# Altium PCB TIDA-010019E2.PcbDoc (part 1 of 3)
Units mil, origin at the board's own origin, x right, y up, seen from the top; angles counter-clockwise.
Board outline 3159.64 x 4813.18 mil, 2 copper layers (Top Layer, Bottom Layer), stack 62 mil thick; 303 components, 177 nets, 861 pads, 1443 vias.
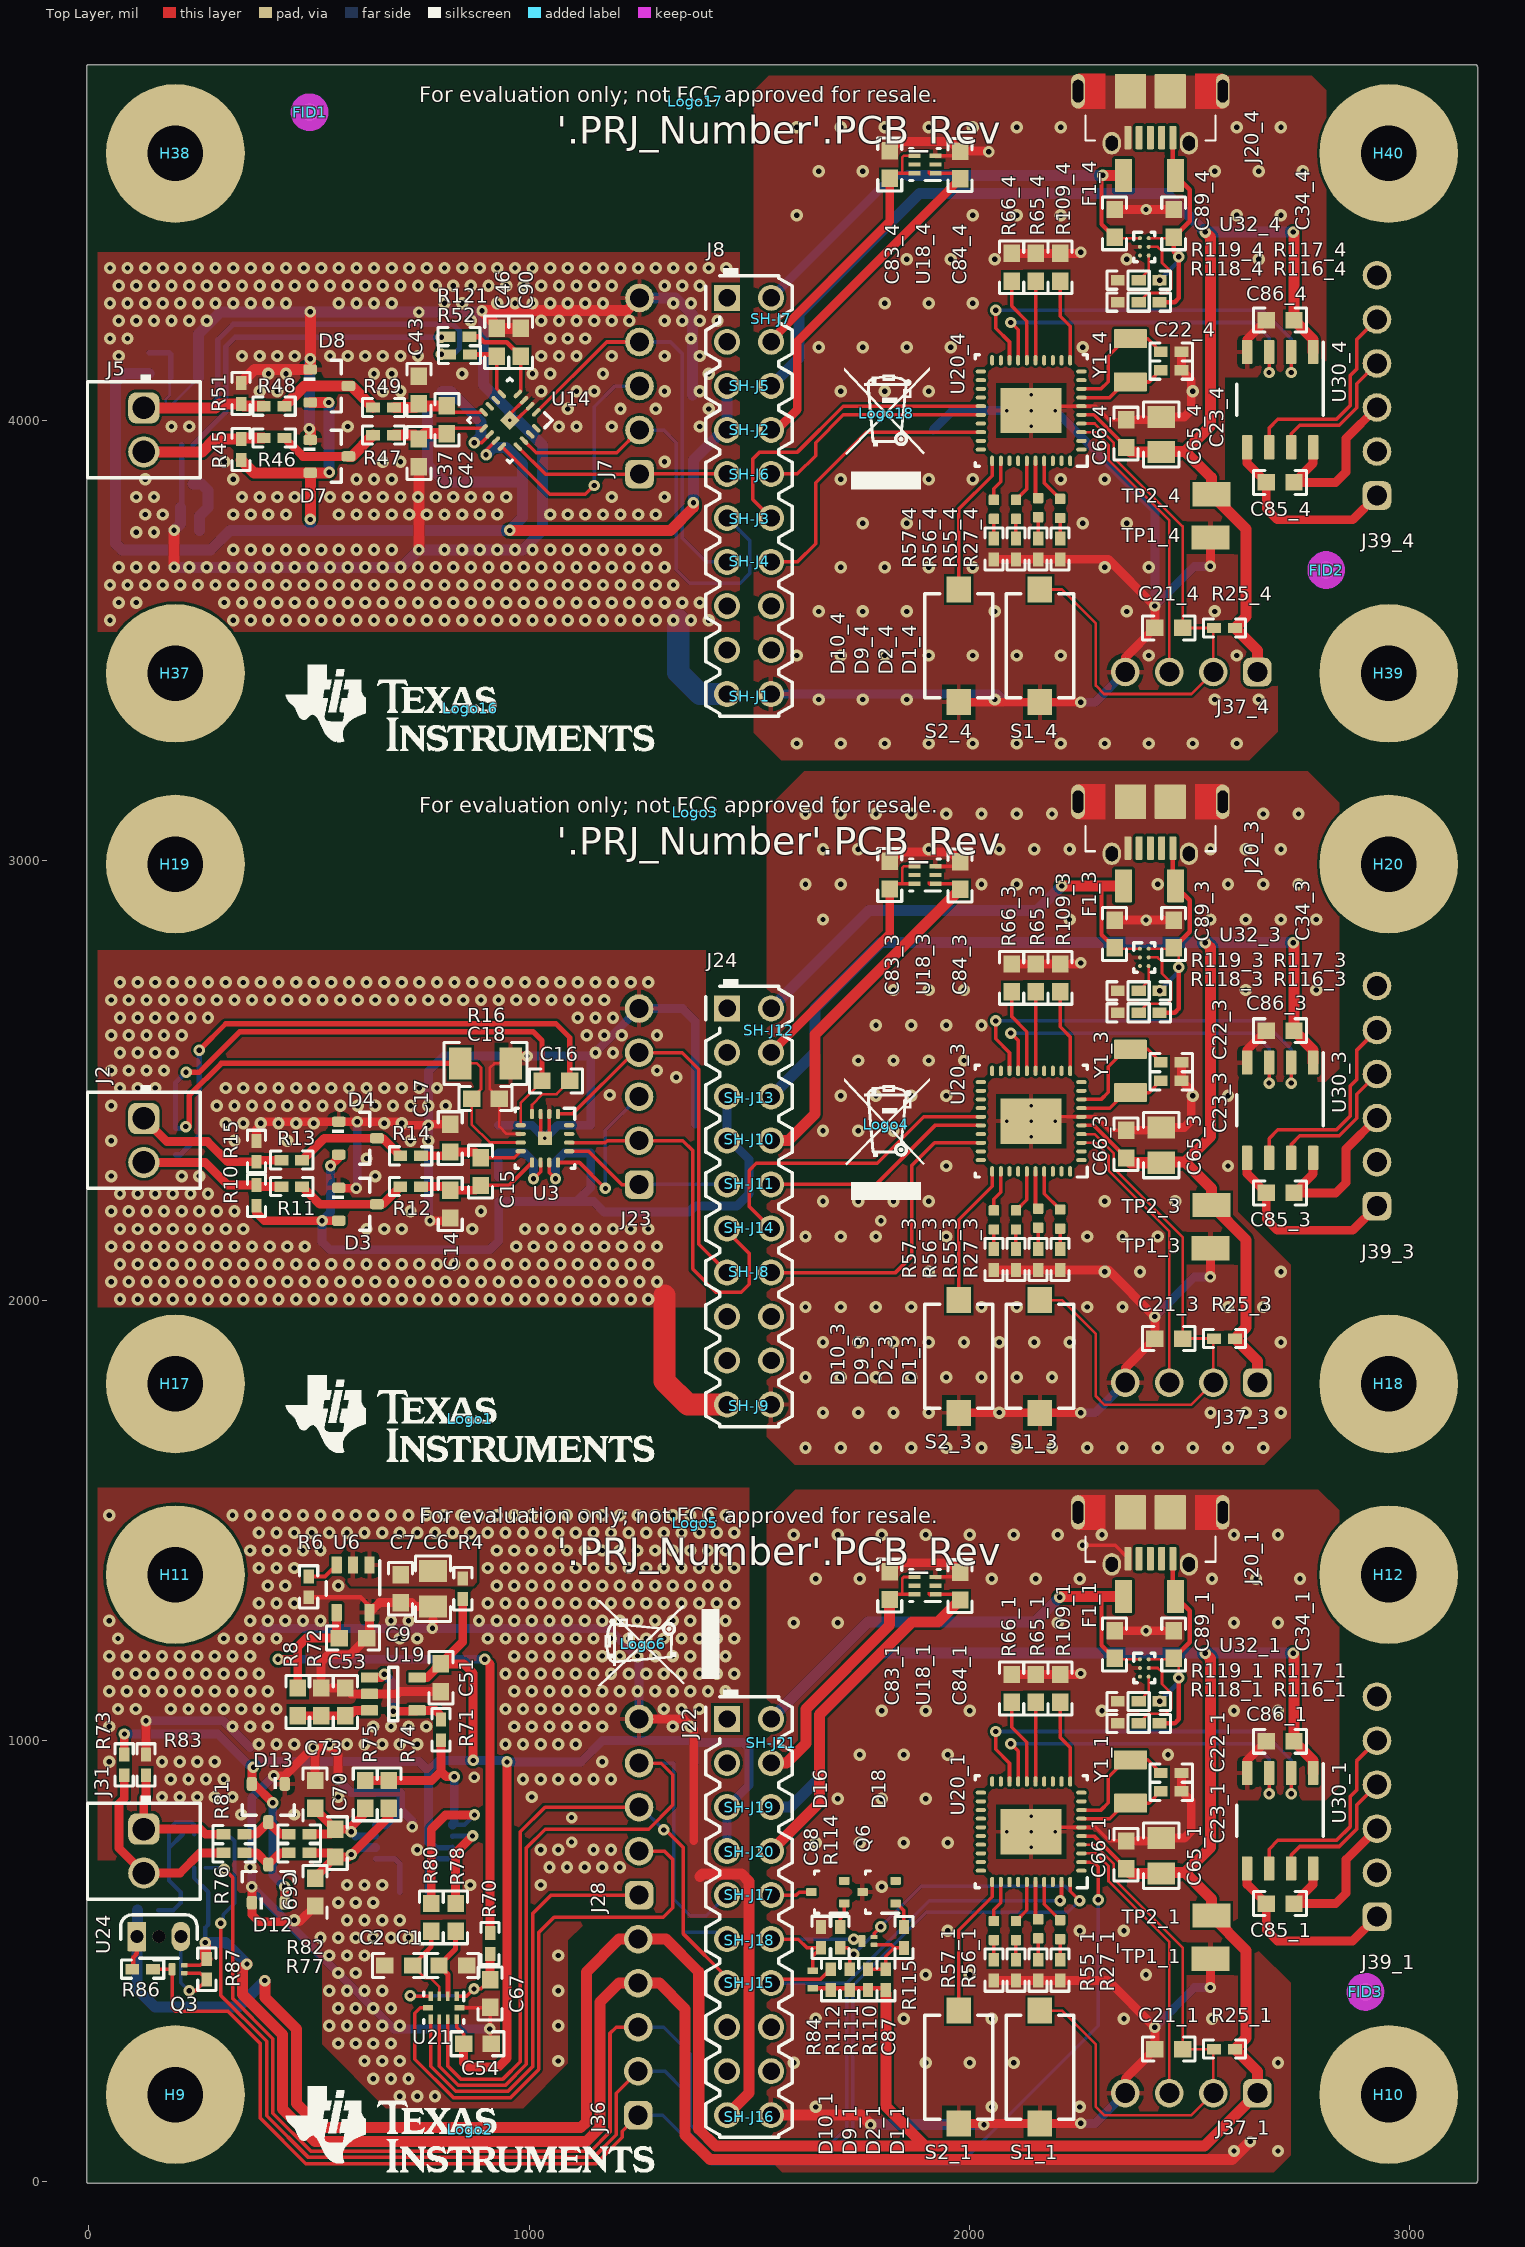
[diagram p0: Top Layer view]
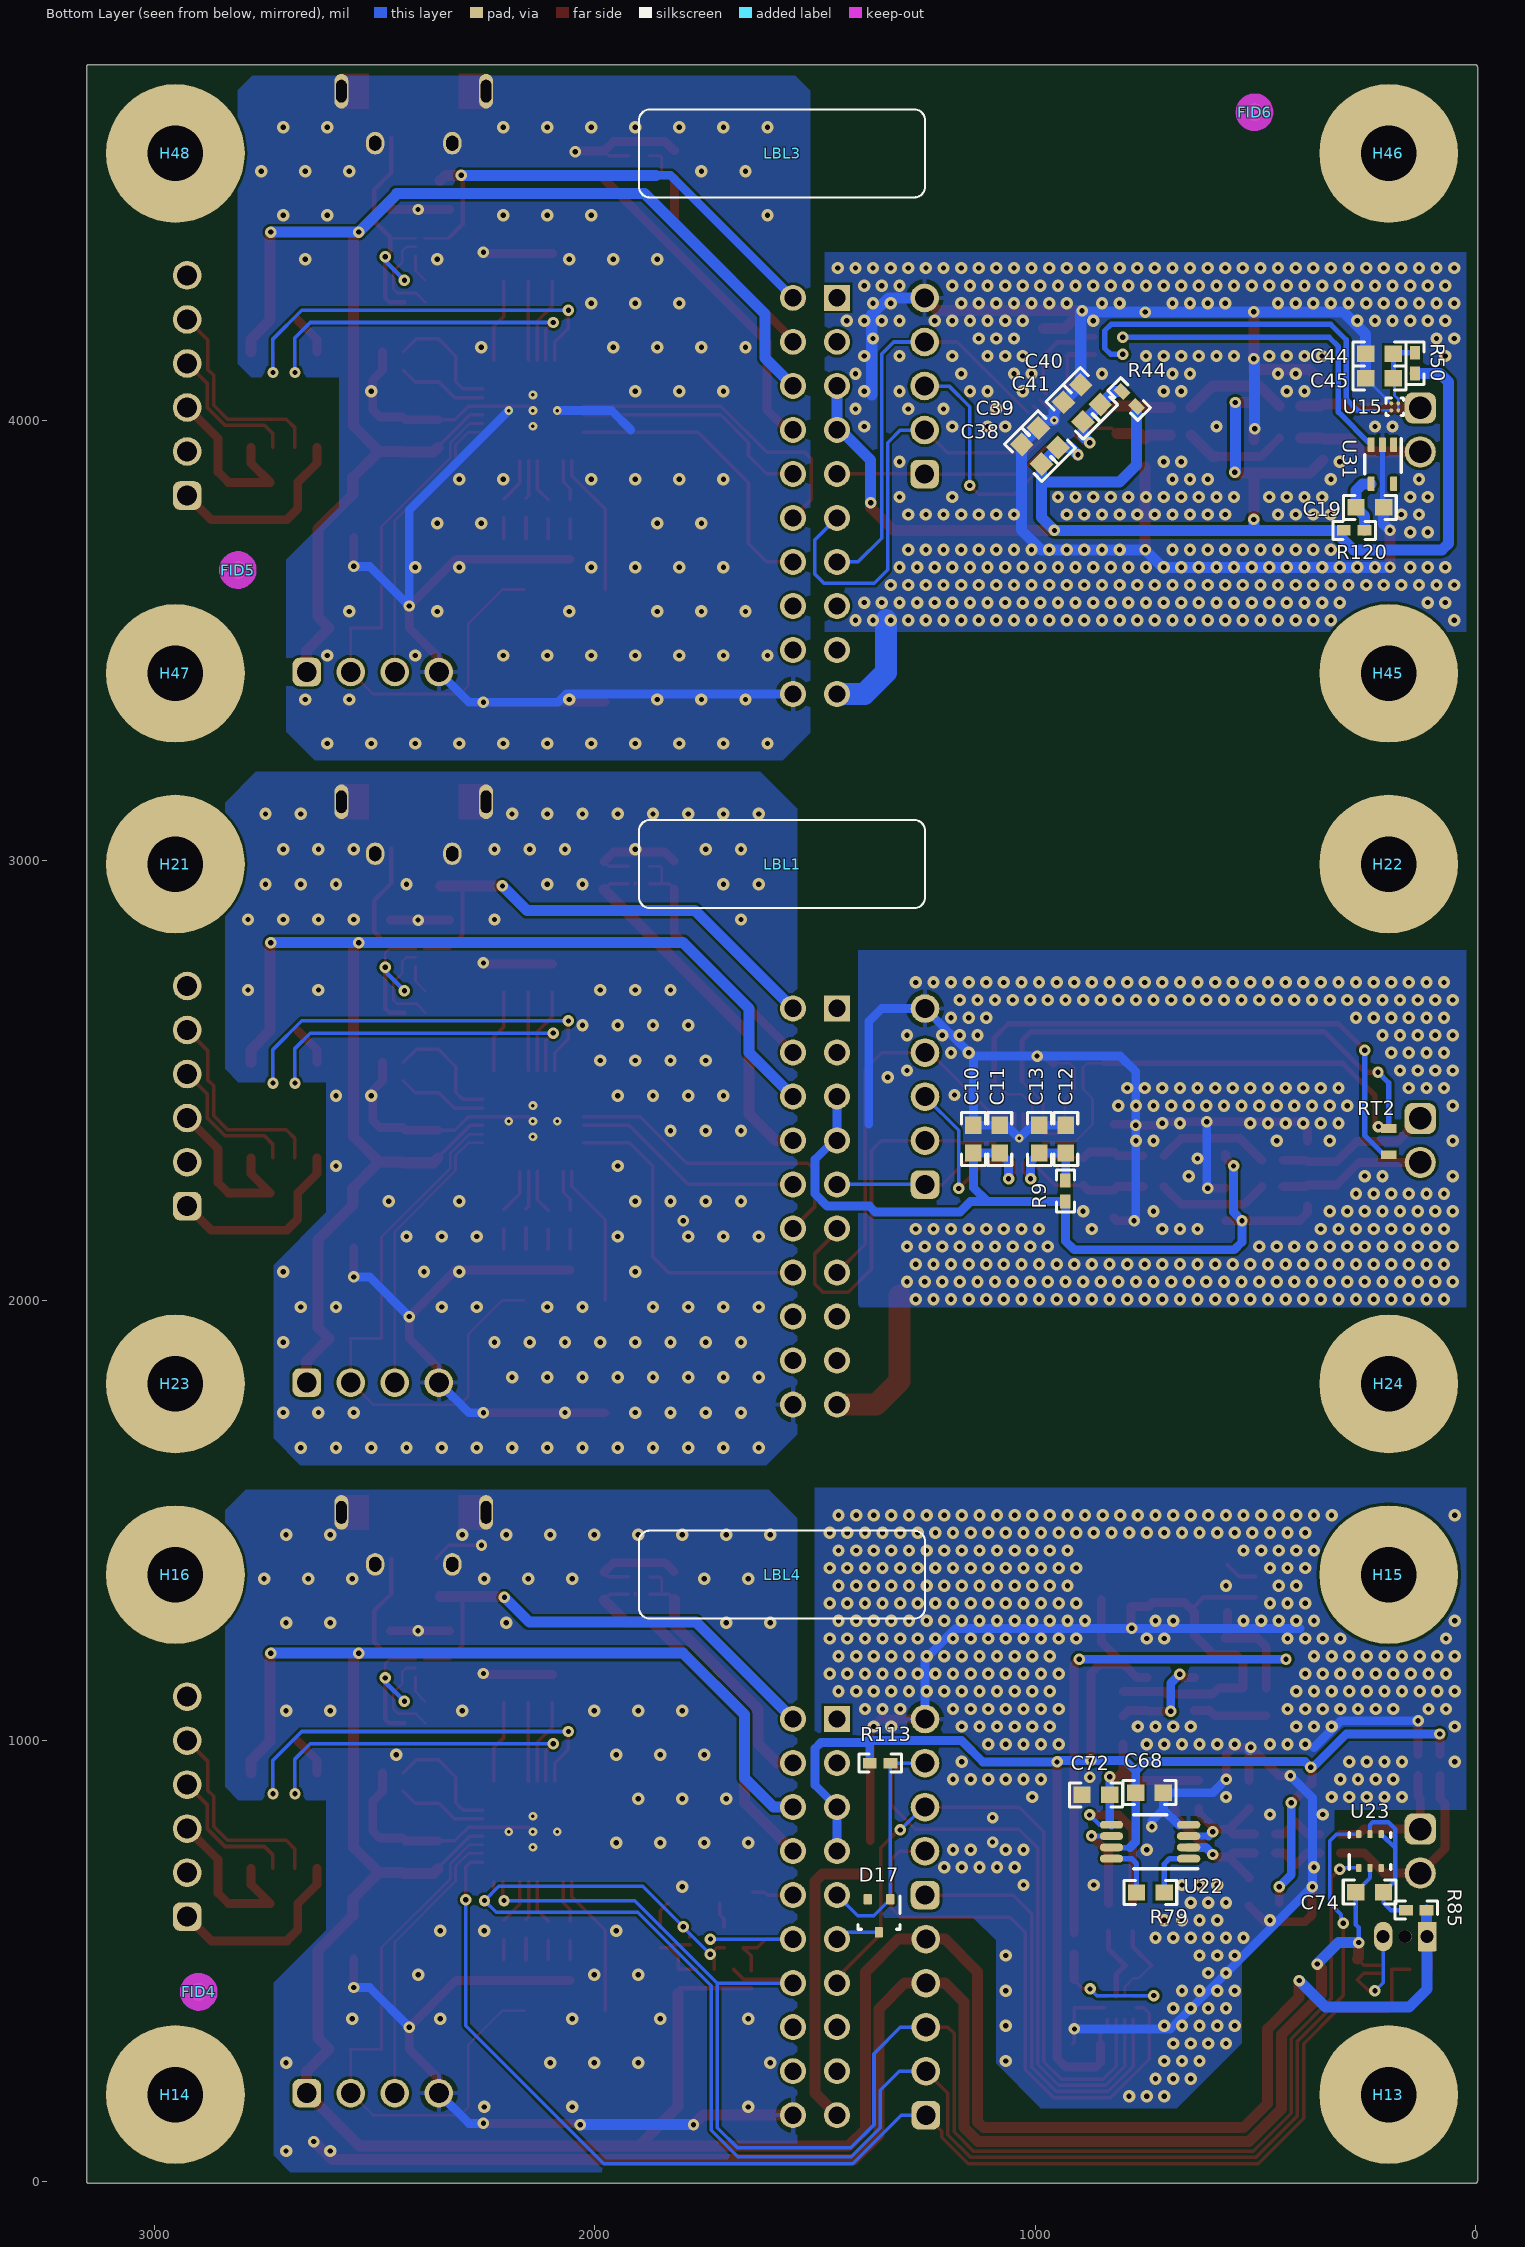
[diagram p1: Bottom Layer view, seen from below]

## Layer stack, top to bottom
Top Solder: solder mask 0.4, Solder Resist, Dk 3.5
Top Layer: signal copper 1.4
Dielectric1: core 59.2, FR-4, Dk 4.8
Bottom Layer: signal copper 1.4
Bottom Solder: solder mask 0.4, Solder Resist, Dk 3.5

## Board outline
-5.01,0 -5.01,4803.15 cw(c0,4803.15) 0,4808.16 3149.61,4808.16 cw(c3149.61,4803.15) 3154.62,4803.15 3154.62,0 cw(c3149.61,0) 3149.61,-5.02 0,-5.02 cw(c0,0)

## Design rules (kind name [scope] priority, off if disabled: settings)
AcuteAngle [All] p1: minimum=4.00000000000000E+0001 checktracksonly=FALSE
AssemblyTestPointUsage [All] p1: valid=2
BoardOutlineClearance BoardOutlineClearance_MountingHoles [OnCopper and InComponentClass('Mounting Holes')] p1: gap=40 ignorepadtopadclearanceinfootprint=FALSE
BoardOutlineClearance BoardOutlineClearance_Poly [OnCopper and IsPoly] p2: gap=25 ignorepadtopadclearanceinfootprint=FALSE
BoardOutlineClearance [OnCopper and Not InComponentClass('Logo') and not InComponentClass('FiducialMark') and not InRegion(1000,500,4000,800) and not InPoly] p3: gap=20 ignorepadtopadclearanceinfootprint=FALSE
Clearance Clearance_Keepouts [((IsTrack Or IsArc) And Not InPoly) And IsFree and IsKeepOut vs ((IsTrack Or IsArc) And Not InPoly) And IsFree and IsKeepOut] p1: gap=0 ignorepadtopadclearanceinfootprint=FALSE
Clearance Clearance_Poly [InPolygon] p2: gap=6 ignorepadtopadclearanceinfootprint=FALSE
Clearance Clearance_FiducialMark [IsKeepOut and InComponentClass('FiducialMark') vs IsPad and InComponentClass('FiducialMark')] p3: gap=0 ignorepadtopadclearanceinfootprint=FALSE
Clearance [All] p4: gap=6 ignorepadtopadclearanceinfootprint=FALSE
ComponentClearance ComponentClearance_1 [InComponent('SH-J*')  or InComponent('J*')] p1: gap=0 collisioncheckmode=3 verticalgap=0 showdistances=FALSE
ComponentClearance ComponentClearance_J21-J25 [InComponent('J21') or InComponent('J25')] p2: gap=0 collisioncheckmode=3 verticalgap=0 showdistances=FALSE
ComponentClearance ComponentClearance_J1-J35 [InComponent('J1') or InComponent('J35')] p3: gap=0 collisioncheckmode=3 verticalgap=0 showdistances=FALSE
ComponentClearance ComponentClearance_J39-J14-U29 [InComponent('J21') or InComponent('J25') or InComponent('U29')] p4: gap=0 collisioncheckmode=3 verticalgap=0 showdistances=FALSE
ComponentClearance ComponentClearance_R117_R119 [InComponent('R117*') or InComponent('R119*')] p5: gap=0 collisioncheckmode=3 verticalgap=0 showdistances=FALSE
ComponentClearance ComponentClearance_R116_R118 [InComponent('R116*') or InComponent('R118*')] p6: gap=0 collisioncheckmode=3 verticalgap=0 showdistances=FALSE
ComponentClearance ComponentClearance_J11-J18 [InComponent('J11') or InComponent('J18')] p7: gap=0 collisioncheckmode=3 verticalgap=0 showdistances=FALSE
ComponentClearance ComponentClearance_J28-J36 [InComponent('J28') or InComponent('J36')] p8: gap=0 collisioncheckmode=3 verticalgap=0 showdistances=FALSE
ComponentClearance ComponentClearance_MountingHoles_FiducialMarks [InComponentClass('Mounting Holes') vs InComponentClass('FiducialMark')] p9: gap=50 collisioncheckmode=3 verticalgap=10 showdistances=FALSE
ComponentClearance ComponentClearance_Shunt [InComponentClass('Header') vs InComponentClass('Shunt')] p10: gap=0 collisioncheckmode=3 verticalgap=0 showdistances=FALSE
ComponentClearance ComponentClearance_Logo [InComponentClass('Logo')] p11: gap=50 collisioncheckmode=3 verticalgap=10 showdistances=FALSE
ComponentClearance ComponentClearance_ScrewToNut [(HasFootprint('NY PMS 440 0025 PH')) vs (HasFootprint('Keystone_1902C'))] p12: gap=4 collisioncheckmode=3 verticalgap=10 showdistances=FALSE
ComponentClearance ComponentClearance_MountingHoles [InComponentClass('Mounting Holes')] p13: gap=50 collisioncheckmode=3 verticalgap=100000 showdistances=FALSE
ComponentClearance ComponentClearance_SmallPassives [HasFootprint('0201*') or HasFootprint('0402*') or HasFootprint('0508') or HasFootprint('0603*') or HasFootprint('0612') or HasFootprint('0805*') or HasFootprint('0815*') or HasFootprint('0830*') or HasFootprint('1206*') or HasFootprint('1210*') or HasFootprint('1808*') or HasFootprint('1812*') or HasFootprint('1825*') or HasFootprint('2010*') or HasFootprint('2220*') or HasFootprint('2225*') or HasFootprint('2512*') or HasFootprint('2728*') or HasFootprint('3518*') vs HasFootprint('0201*') or HasFootprint('0402*') or HasFootprint('0508') or HasFootprint('0603*') or HasFootprint('0612') or HasFootprint('0805*') or HasFootprint('0815*') or HasFootprint('0830*') or HasFootprint('1206*') or HasFootprint('1210*') or HasFootprint('1808*') or HasFootprint('1812*') or HasFootprint('1825*') or HasFootprint('2010*') or HasFootprint('2220*') or HasFootprint('2225*') or HasFootprint('2512*') or HasFootprint('2728*') or HasFootprint('3518*')] p14: gap=14.96 collisioncheckmode=3 verticalgap=10 showdistances=FALSE
ComponentClearance ComponentClearance_THtoSMT [IsThruComponent vs IsSMTComponent] p15: gap=30 collisioncheckmode=3 verticalgap=30 showdistances=FALSE
ComponentClearance ComponentClearance_THtoTH [IsThruComponent vs IsThruComponent] p16: gap=30 collisioncheckmode=3 verticalgap=30 showdistances=FALSE
ComponentClearance [All] p17: gap=25 collisioncheckmode=3 verticalgap=10 showdistances=FALSE
DiffPairsRouting [All] p1: maxlimit=100 minlimit=10 mostfreqgap=10 toplayer_minwidth=15 toplayer_maxwidth=15 toplayer_prefwidth=15 bottomlayer_minwidth=15 bottomlayer_maxwidth=15 bottomlayer_prefwidth=15 maxuncoupledlength=1000
FabricationTestPointUsage TestPointUsage [All] p1: valid=2 allowmultiple=FALSE
FabricationTestpoint Testpoint [All] p1: side=3 testpointundercomponent=TRUE minsize=40 maxsize=100 preferedsize=60 minholesize=0 maxholesize=40 preferedholesize=32 testpointgrid=1 allowsidetop=TRUE allowsidebottom=TRUE usegrid=TRUE gridtolerance=0.01
FanoutControl Fanout_LCC [IsLCC] p1: bgadir=Out bgaviamode=Centered fanoutstyle=Auto fanoutdirection=Alternating viagrid=1 // Fanout_LCC (Default Rule)
FanoutControl Fanout_BGA [IsBGA] p2: bgadir=Out bgaviamode=Centered fanoutstyle=Auto fanoutdirection=Alternating viagrid=1 // Fanout_BGA (Default Rule)
FanoutControl Fanout_Default [All] p4: bgadir=Out bgaviamode=Centered fanoutstyle=Auto fanoutdirection=Alternating viagrid=1 // Fanout_Default (Default Rule)
FanoutControl Fanout_Small [(CompPinCount < 5)] p5: bgadir=Out bgaviamode=Centered fanoutstyle=Auto fanoutdirection=OutThenIn viagrid=1 // Fanout_Small (Default Rule)
HoleSize [All] p1: absolutevalues=TRUE maxlimit=251 minlimit=7.87 maxpercent=80.000 minpercent=20.000
MinimumAnnularRing MinimumAnnularRing_ThermalPadVias [IsVia and InAnyComponent] p1: minimumring=5.91
MinimumAnnularRing [All] p2: minimumring=6
MinimumSolderMaskSliver MinimumSolderMaskSliver_Logo [InComponentClass('Logo') vs InComponentClass('Logo')] p1: minsoldermaskwidth=0.7
MinimumSolderMaskSliver [All] p2: minsoldermaskwidth=3.94
PlaneConnect [All] p1: planeconnectstyle=Relief reliefexpansion=10 reliefentries=4 reliefconductorwidth=10 reliefairgap=10
PolygonConnect PolygonConnect_direct [HasFootprint('0402*') or HasFootprint('0603*') or HasFootprint('0805*') or IsVia or InComponent('J20*')] p1: connectstyle=Direct reliefconductorwidth=10 reliefentries=4 polygonreliefangle="90 Angle" airgapwidth=10
PolygonConnect [All] p2: connectstyle=Relief reliefconductorwidth=10 reliefentries=4 polygonreliefangle="90 Angle" airgapwidth=10
RoomDefinition 4 [InComponentClass('4')] p1: confinementstyle=ConfineIn formatcopy=TRUE lockcomponents=FALSE outline 2986.21,3227.72 1726.21,3227.72 1726.21,4802.52 2986.21,4802.52
RoomDefinition 3 [InComponentClass('3')] p2: confinementstyle=ConfineIn formatcopy=TRUE lockcomponents=FALSE outline 2986.22,1613.55 1726.22,1613.55 1726.22,3188.35 2986.22,3188.35
RoomDefinition 1 [InComponentClass('1')] p3: confinementstyle=ConfineIn formatcopy=TRUE lockcomponents=TRUE outline 2986.22,-0.62 1726.22,-0.62 1726.22,1574.18 2986.22,1574.18
RoutingVias ThermalPadVias [IsVia and InAnyComponent] p1: holewidth=7.87 width=19.68 viastyle="Through Hole" minholewidth=7.87 minwidth=19.68 maxholewidth=12.99 maxwidth=23.62
RoutingVias [All] p2: holewidth=12 width=26 viastyle="Through Hole" minholewidth=7.87 minwidth=24 maxholewidth=40 maxwidth=65
SilkToBoardRegionClearance [Not ((IsComment or IsDesignator) And (Hide <> 'False')) and not InRegion(1000,500,4000,800)] p1:
SilkToSilkClearance SilkToSilkClearance_Pb-FreeLogo [(HasFootprint('Pb-Free_Overlay_Medium') OR HasFootprint('Pb-Free_Overlay_Small')) vs (HasFootprint('Pb-Free_Overlay_Medium') OR HasFootprint('Pb-Free_Overlay_Small'))] p1: silktosilkclearance=0
SilkToSilkClearance [All] p2: silktosilkclearance=4
SilkToSolderMaskClearance SilkToComponentPadClearance [(IsPad or IsFill or IsRegion) and InAnycomponent] p1: minsilkscreentomaskgap=2 clearancetoexposedcopper=TRUE
SilkToSolderMaskClearance "Silk to Solder Mask Opening" [All] p2: minsilkscreentomaskgap=2 clearancetoexposedcopper=FALSE
SolderMaskExpansion [All] p1: expansion=1.97
Width [All] p1: maxlimit=100 minlimit=6 preferedwidth=10 checkconnectedcopper=TRUE
15 further rules are at their usual default settings.

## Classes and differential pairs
component class Shunt: SH-J1 SH-J2 SH-J3 SH-J4 SH-J5 SH-J6 SH-J7 SH-J8 SH-J9 SH-J10 SH-J11 SH-J12 SH-J13 SH-J14 SH-J15 SH-J16 SH-J17 SH-J18 SH-J19 SH-J20 SH-J21
component class INA_7142: C1 C2 C6 C7 C9 C51 C53 C54 C67 C68 C69 C70 C72 C73 C74 C87 C88 D12 D13 D16 D17 D18 J22 J28 J31 J36 Q3 Q6 R4 R6 R8 R70 R71 R72 R73 R74 R75 R76 R77 R78 R79 R80 R81 R82 R83 R84 R85 R86 R87 R110 R111 R112 R113 R114 R115 SH-J15 SH-J16 SH-J17 SH-J18 SH-J19 SH-J20 SH-J21 U6 U19 U21 U22 U23 U24
channel class MCU: 0 1 2 3 4 5
net class Hardware_Nets: NetH1_1 NetH2_1 NetH3_1 NetH4_1
net class 4_Nets: NetC21_4_1 NetC22_4_1 NetC23_4_1 NetC34_4_1 NetC85_4_1 NetC85_4_2 NetD1_4_1 NetD1_4_2 NetD2_4_1 NetD2_4_2 NetD9_4_1 NetD9_4_2 NetD10_4_1 NetD10_4_2 NetJ37_4_3 NetJ37_4_5 NetJ37_4_6 NetJ37_4_8 NetJ37_4_10 NetJ37_4_11 NetJ37_4_12 NetJ37_4_13 NetJ37_4_14 NetJ39_4_2 NetJ39_4_4 NetJ39_4_5 NetJ39_4_6 NetR65_4_2 NetR66_4_2 NetR109_4_2 NetR116_4_1 NetR117_4_1 NetS2_4_2 NetU18_4_4 NetU20_4_1 NetU20_4_9 NetU20_4_10 NetU20_4_11 NetU20_4_12 NetU20_4_13 NetU20_4_14 NetU20_4_17 NetU20_4_18 NetU20_4_19 NetU20_4_20 NetU20_4_21 NetU20_4_22 NetU20_4_23 NetU20_4_24 NetU20_4_29 NetU20_4_30 NetU20_4_33 NetU20_4_34
net class 3_Nets: NetC21_3_1 NetC22_3_1 NetC23_3_1 NetC34_3_1 NetC85_3_1 NetC85_3_2 NetD1_3_1 NetD1_3_2 NetD2_3_1 NetD2_3_2 NetD9_3_1 NetD9_3_2 NetD10_3_1 NetD10_3_2 NetJ37_3_3 NetJ37_3_5 NetJ37_3_6 NetJ37_3_8 NetJ37_3_10 NetJ37_3_11 NetJ37_3_12 NetJ37_3_13 NetJ37_3_14 NetJ39_3_2 NetJ39_3_4 NetJ39_3_5 NetJ39_3_6 NetR65_3_2 NetR66_3_2 NetR109_3_2 NetR116_3_1 NetR117_3_1 NetS2_3_2 NetU18_3_4 NetU20_3_1 NetU20_3_9 NetU20_3_10 NetU20_3_11 NetU20_3_12 NetU20_3_13 NetU20_3_14 NetU20_3_17 NetU20_3_18 NetU20_3_19 NetU20_3_20 NetU20_3_21 NetU20_3_22 NetU20_3_23 NetU20_3_24 NetU20_3_29 NetU20_3_30 NetU20_3_33 NetU20_3_34
net class 1_Nets: NetC21_1_1 NetC22_1_1 NetC23_1_1 NetC34_1_1 NetC85_1_1 NetC85_1_2 NetD1_1_1 NetD1_1_2 NetD2_1_1 NetD2_1_2 NetD9_1_1 NetD9_1_2 NetD10_1_1 NetD10_1_2 NetJ37_1_3 NetJ37_1_5 NetJ37_1_6 NetJ37_1_8 NetJ37_1_10 NetJ37_1_11 NetJ37_1_12 NetJ37_1_13 NetJ37_1_14 NetJ39_1_2 NetJ39_1_4 NetJ39_1_5 NetJ39_1_6 NetR65_1_2 NetR66_1_2 NetR109_1_2 NetR116_1_1 NetR117_1_1 NetS2_1_2 NetU18_1_4 NetU20_1_1 NetU20_1_9 NetU20_1_10 NetU20_1_11 NetU20_1_12 NetU20_1_13 NetU20_1_14 NetU20_1_17 NetU20_1_18 NetU20_1_19 NetU20_1_20 NetU20_1_21 NetU20_1_22 NetU20_1_23 NetU20_1_24 NetU20_1_29 NetU20_1_30 NetU20_1_33 NetU20_1_34
component class LMT70: C19 C37 C38 C39 C40 C41 C42 C43 C44 C45 C46 C90 D7 D8 J5 J7 J8 R44 R45 R46 R47 R48 R49 R50 R51 R52 R120 R121 SH-J1 SH-J2 SH-J3 SH-J4 SH-J5 SH-J6 SH-J7 U14 U15 U31
component class 4: C21_4 C22_4 C23_4 C34_4 C65_4 C66_4 C83_4 C84_4 C85_4 C86_4 C89_4 D1_4 D2_4 D9_4 D10_4 F1_4 J20_4 J37_4 J39_4 R25_4 R27_4 R55_4 R56_4 R57_4 R65_4 R66_4 R109_4 R116_4 R117_4 R118_4 R119_4 S1_4 S2_4 TP1_4 TP2_4 U18_4 U20_4 U30_4 U32_4 Y1_4
component class 3: C21_3 C22_3 C23_3 C34_3 C65_3 C66_3 C83_3 C84_3 C85_3 C86_3 C89_3 D1_3 D2_3 D9_3 D10_3 F1_3 J20_3 J37_3 J39_3 R25_3 R27_3 R55_3 R56_3 R57_3 R65_3 R66_3 R109_3 R116_3 R117_3 R118_3 R119_3 S1_3 S2_3 TP1_3 TP2_3 U18_3 U20_3 U30_3 U32_3 Y1_3
component class 1: C21_1 C22_1 C23_1 C34_1 C65_1 C66_1 C83_1 C84_1 C85_1 C86_1 C89_1 D1_1 D2_1 D9_1 D10_1 F1_1 J20_1 J37_1 J39_1 R25_1 R27_1 R55_1 R56_1 R57_1 R65_1 R66_1 R109_1 R116_1 R117_1 R118_1 R119_1 S1_1 S2_1 TP1_1 TP2_1 U18_1 U20_1 U30_1 U32_1 Y1_1
net class RTD_Nets: 3.3V_8 GND_8 NetC12_1 NetC14_1 NetC15_2 NetC16_1 NetC16_2 NetD3_3 NetD4_3 NetJ2_1 NetJ2_2 NetJ23_1 NetJ23_2 NetJ23_3 NetJ23_4 NetU3_1 NetU3_12 NetU3_13 NetU3_14 NetU3_15 NetU3_16
net class LMT70_Nets: 3.3V_11 GND_11 NetC19_1 NetC37_1 NetC40_1 NetC42_2 NetC44_1 NetC46_1 NetC90_1 NetD7_3 NetD8_3 NetJ5_1 NetJ5_2 NetJ7_1 NetJ7_2 NetJ7_3 NetJ7_4 NetR52_2 NetR121_2 NetU14_1 NetU14_2 NetU14_3 NetU14_6 NetU14_8 NetU14_9 NetU14_14 NetU14_15 NetU14_16
component class RTD: C10 C11 C12 C13 C14 C15 C16 C17 C18 D3 D4 J2 J23 J24 R9 R10 R11 R12 R13 R14 R15 R16 RT2 SH-J8 SH-J9 SH-J10 SH-J11 SH-J12 SH-J13 SH-J14 U3
component class Hardware: !PCB FID1 FID2 FID3 FID4 FID5 FID6 H9 H10 H11 H12 H13 H14 H15 H16 H17 H18 H19 H20 H21 H22 H23 H24 H37 H38 H39 H40 H45 H46 H47 H48 LBL1 LBL3 LBL4 Logo3 Logo4 Logo5 Logo6 Logo17 Logo18 ZZ1 ZZ2 ZZ3 ZZ4
component class "Mounting Holes": H9 H10 H11 H12 H17 H18 H19 H20 H37 H38 H39 H40
component class Label: LBL1 LBL3 LBL4
component class FiducialMark: FID1 FID2 FID3 FID4 FID5 FID6
component class AssemblyNote: ZZ1 ZZ2 ZZ3 ZZ4
component class Header: J7 J8 J22 J23 J24 J28 J36 J37_1 J37_3 J37_4 J39_1 J39_3 J39_4

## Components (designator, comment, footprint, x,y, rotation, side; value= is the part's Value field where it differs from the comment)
C1 "885012206020" 0603 826.88,489.98 r0 top value=0.1uF
C2 "885012206020" 0603 704.09,489.98 r180 top value=0.1uF
C6 "885012207026" 0805_HV 782.08,1345.83 r270 top value=10uF
C7 "885012206020" 0603 708.26,1345.83 r270 top value=0.1uF
C9 "885012206020" 0603 600.23,1233.62 r0 top value=0.1uF
C10 "885012106017" 0603 1140.18,2367.25 r90 bottom value=1uF
C11 "885012206020" 0603 1080.18,2367.25 r90 bottom value=0.1uF
C12 "885012106017" 0603 930.18,2367.25 r90 bottom value=1uF
C13 "885012206020" 0603 990.18,2367.25 r90 bottom value=0.1uF
C14 "C1608NP01H103J080AA" 0603 821.06,2219.41 r270 top value=0.01uF
C15 "885012206020" 0603 890,2293.39 r90 top value=0.1uF
C16 "885012106017" 0603 1061.06,2499.41 r0 top value=1uF
C17 "C1608NP01H103J080AA" 0603 821.06,2369.41 r90 top value=0.01uF
C18 "885012106017" 0603 901.06,2459.41 r0 top value=1uF
C19 "885012206020" 0603 239.53,3802.08 r180 bottom value=0.1uF
C21_1 "C0603C102K3GACTU" 0603 2453.22,300 r180 top value=1000pF (schematic designator C21)
C21_3 "C0603C102K3GACTU" 0603 2453.22,1914.17 r180 top value=1000pF (schematic designator C21)
C21_4 "C0603C102K3GACTU" 0603 2453.21,3528.34 r180 top value=1000pF (schematic designator C21)
C22_1 "GRM1555C1E120JA01D" 0402 2458.74,927.33 r0 top value=12pF (schematic designator C22)
C22_3 "GRM1555C1E120JA01D" 0402 2458.74,2541.5 r0 top value=12pF (schematic designator C22)
C22_4 "GRM1555C1E120JA01D" 0402 2458.73,4155.67 r0 top value=12pF (schematic designator C22)
C23_1 "GRM1555C1E120JA01D" 0402 2458.74,885.6 r0 top value=12pF (schematic designator C23)
C23_3 "GRM1555C1E120JA01D" 0402 2458.74,2499.77 r0 top value=12pF (schematic designator C23)
C23_4 "GRM1555C1E120JA01D" 0402 2458.73,4113.94 r0 top value=12pF (schematic designator C23)
C34_1 "CL10B105KP8NNNC" 0603 2464.55,1219.11 r90 top value=1uF (schematic designator C34)
C34_3 "CL10B105KP8NNNC" 0603 2464.55,2833.28 r90 top value=1uF (schematic designator C34)
C34_4 "CL10B105KP8NNNC" 0603 2464.54,4447.45 r90 top value=1uF (schematic designator C34)
C37 "C1608NP01H103J080AA" 0603 749.99,3926.05 r270 top value=0.01uF
C38 "885012106017" 0603 1007.67,3922.91 r45 bottom value=1uF
C39 "885012206020" 0603 970.08,3960.5 r45 bottom value=0.1uF
C40 "885012106017" 0603 873.98,4058.31 r45 bottom value=1uF
C41 "885012206020" 0603 913.37,4018.94 r45 bottom value=0.1uF
C42 "885012206020" 0603 813.43,4001.34 r90 top value=0.1uF
C43 "C1608NP01H103J080AA" 0603 749.99,4068.87 r90 top value=0.01uF
C44 "885012106017" 0603 217.51,4150.92 r0 bottom value=1uF
C45 "885012206020" 0603 217.51,4096.13 r0 bottom value=0.1uF
C46 "C1608X5R1H473K080AA" 0603 926.81,4177.48 r90 top value=0.047uF
C51 "885012206020" 0603 799.61,1143.73 r270 top value=0.1uF
C53 "885012206020" 0603 582.92,1088.79 r90 top value=0.1uF
C54 "885012106017" 0603 882.99,312.2 r0 top value=1uF
C65_1 "885012207026" 0805_HV 2436.22,739.38 r90 top value=10uF (schematic designator C65)
C65_3 "885012207026" 0805_HV 2436.22,2353.55 r90 top value=10uF (schematic designator C65)
C65_4 "885012207026" 0805_HV 2436.21,3967.72 r90 top value=10uF (schematic designator C65)
C66_1 "885012206020" 0603 2356.22,741.5 r90 top value=0.1uF (schematic designator C66)
C66_3 "885012206020" 0603 2356.22,2355.68 r90 top value=0.1uF (schematic designator C66)
C66_4 "885012206020" 0603 2356.21,3969.85 r90 top value=0.1uF (schematic designator C66)
C67 "885012106017" 0603 911.54,426.42 r270 top value=1uF
C68 "885012206020" 0603 740,882.52 r180 bottom value=0.1uF
C69 "885012206020" 0603 514.06,656.78 r90 top value=0.1uF
C70 "GCM188R71C105MA64D" 0603 560,767.89 r90 top value=1uF
C72 "885012206020" 0603 861.73,877.53 r0 bottom value=0.1uF
C73 "885012206020" 0603 514.06,878.74 r90 top value=0.1uF
C74 "885012106017" 0603 240,656.78 r0 bottom value=1uF
C83_1 "CL10B105KP8NNNC" 0603 1819.45,1352.9 r90 top value=1uF (schematic designator C83)
C83_3 "CL10B105KP8NNNC" 0603 1819.45,2967.08 r90 top value=1uF (schematic designator C83)
C83_4 "CL10B105KP8NNNC" 0603 1819.44,4581.24 r90 top value=1uF (schematic designator C83)
C84_1 "CL10B105KP8NNNC" 0603 1979.45,1351.8 r90 top value=1uF (schematic designator C84)
C84_3 "CL10B105KP8NNNC" 0603 1979.45,2965.97 r90 top value=1uF (schematic designator C84)
C84_4 "CL10B105KP8NNNC" 0603 1979.44,4580.14 r90 top value=1uF (schematic designator C84)
C85_1 "885012206020" 0603 2706.22,630.8 r0 top value=0.1uF (schematic designator C85)
C85_3 "885012206020" 0603 2706.22,2244.97 r0 top value=0.1uF (schematic designator C85)
C85_4 "885012206020" 0603 2706.21,3859.14 r0 top value=0.1uF (schematic designator C85)
C86_1 "885012206020" 0603 2706.22,999.38 r180 top value=0.1uF (schematic designator C86)
C86_3 "885012206020" 0603 2706.22,2613.55 r180 top value=0.1uF (schematic designator C86)
C86_4 "885012206020" 0603 2706.21,4227.72 r180 top value=0.1uF (schematic designator C86)
C87 "GCM155R71H103KA55D" 0402 1810.76,457.91 r90 top value=0.01uF
C88 "885012005055" 0402 1663.35,553.94 r90 top value=10pF
C89_1 "CL10B105KP8NNNC" 0603 2330.28,1219.11 r90 top value=1uF (schematic designator C89)
C89_3 "CL10B105KP8NNNC" 0603 2330.28,2833.28 r90 top value=1uF (schematic designator C89)
C89_4 "CL10B105KP8NNNC" 0603 2330.28,4447.45 r90 top value=1uF (schematic designator C89)
C90 "C1608X5R1H473K080AA" 0603 981.02,4177.48 r90 top value=0.047uF
D1_1 "150040GS73240" WL-SMCC_0402_Green 2206.46,571.49 r90 top value=Green (schematic designator D1)
D1_3 "150040GS73240" WL-SMCC_0402_Green 2206.46,2185.66 r90 top value=Green (schematic designator D1)
D1_4 "150040GS73240" WL-SMCC_0402_Green 2206.45,3799.83 r90 top value=Green (schematic designator D1)
D2_1 "150040GS73240" WL-SMCC_0402_Green 2156.46,573.46 r90 top value=Green (schematic designator D2)
D2_3 "150040GS73240" WL-SMCC_0402_Green 2156.46,2187.63 r90 top value=Green (schematic designator D2)
D2_4 "150040GS73240" WL-SMCC_0402_Green 2156.45,3801.8 r90 top value=Green (schematic designator D2)
D3 "BAV199-TP" SOT-23L 611.06,2219.41 r0 top value=70V
D4 "BAV199-TP" SOT-23L 611.06,2369.41 r0 top value=70V
D7 "BAV199-TP" SOT-23L 546.42,3918.16 r0 top value=70V
D8 "BAV199-TP" SOT-23L 546.42,4078 r0 top value=70V
D9_1 "150040GS73240" WL-SMCC_0402_Green 2106.22,569.38 r90 top value=Green (schematic designator D9)
D9_3 "150040GS73240" WL-SMCC_0402_Green 2106.22,2183.55 r90 top value=Green (schematic designator D9)
D9_4 "150040GS73240" WL-SMCC_0402_Green 2106.21,3797.72 r90 top value=Green (schematic designator D9)
D10_1 "150040GS73240" WL-SMCC_0402_Green 2056.06,569.38 r90 top value=Green (schematic designator D10)
D10_3 "150040GS73240" WL-SMCC_0402_Green 2056.06,2183.55 r90 top value=Green (schematic designator D10)
D10_4 "150040GS73240" WL-SMCC_0402_Green 2056.06,3797.72 r90 top value=Green (schematic designator D10)
D12 "BAV199-TP" SOT-23L 408,675.98 r90 top value=70V
D13 "BAV199-TP" SOT-23L 408,859.05 r270 top value=70V
D16 "BAS40W-7-F" SOT-323 1678.84,656.73 r180 top value=40V
D17 "BAS40W-7-F" SOT-323 1354.59,602.95 r270 bottom value=40V
D18 "BAS40W-7-F" SOT-323 1795.27,656.73 r180 top value=40V
F1_1 "0ZCJ0005FF2E" FUSE_0ZCJ_085 2409.53,1328.3 r0 top (schematic designator F1)
F1_3 "0ZCJ0005FF2E" FUSE_0ZCJ_085 2409.53,2942.47 r0 top (schematic designator F1)
F1_4 "0ZCJ0005FF2E" FUSE_0ZCJ_085 2409.52,4556.64 r0 top (schematic designator F1)
FID1 "Fiducial" Fiducial10-20 501.53,4700 r0 top
FID2 "Fiducial" Fiducial10-20 2811.02,3660 r0 top
FID3 "Fiducial" Fiducial10-20 2900,430 r0 top
FID4 "Fiducial" Fiducial10-20 2900,430 r180 bottom
FID5 "Fiducial" Fiducial10-20 2811.02,3660 r180 bottom
FID6 "Fiducial" Fiducial10-20 501.53,4700 r180 bottom
H9 "NY PMS 440 0025 PH" "NY PMS 440 0025 PH" 196.85,196.85 r0 top locked
H10 "NY PMS 440 0025 PH" "NY PMS 440 0025 PH" 2952.76,196.85 r0 top locked
H11 "NY PMS 440 0025 PH" "NY PMS 440 0025 PH" 196.85,1377.95 r0 top
H12 "NY PMS 440 0025 PH" "NY PMS 440 0025 PH" 2952.76,1377.95 r0 top locked
H13 "1902C" Keystone_1902C 197.21,196.85 r180 bottom locked
H14 "1902C" Keystone_1902C 2953.11,196.85 r180 bottom locked
H15 "1902C" Keystone_1902C 197.21,1377.95 r180 bottom locked
H16 "1902C" Keystone_1902C 2953.11,1377.95 r180 bottom locked
H17 "NY PMS 440 0025 PH" "NY PMS 440 0025 PH" 196.85,1811.02 r0 top locked
H18 "NY PMS 440 0025 PH" "NY PMS 440 0025 PH" 2952.76,1811.02 r0 top locked
H19 "NY PMS 440 0025 PH" "NY PMS 440 0025 PH" 196.85,2992.13 r0 top locked
H20 "NY PMS 440 0025 PH" "NY PMS 440 0025 PH" 2952.76,2992.13 r0 top locked
H21 "1902C" Keystone_1902C 2953.11,2992.13 r180 bottom locked
H22 "1902C" Keystone_1902C 197.21,2992.13 r180 bottom locked
H23 "1902C" Keystone_1902C 2953.11,1811.02 r180 bottom locked
H24 "1902C" Keystone_1902C 196.85,1811.02 r180 bottom locked
H37 "NY PMS 440 0025 PH" "NY PMS 440 0025 PH" 196.85,3425.2 r0 top locked
H38 "NY PMS 440 0025 PH" "NY PMS 440 0025 PH" 196.85,4606.3 r0 top locked
H39 "NY PMS 440 0025 PH" "NY PMS 440 0025 PH" 2952.76,3425.2 r0 top locked
H40 "NY PMS 440 0025 PH" "NY PMS 440 0025 PH" 2952.76,4606.3 r0 top locked
H45 "1902C" Keystone_1902C 197.21,3425.2 r180 bottom locked
H46 "1902C" Keystone_1902C 197.21,4606.3 r180 bottom locked
H47 "1902C" Keystone_1902C 2953.11,3425.2 r180 bottom locked
H48 "1902C" Keystone_1902C 2953.11,4606.3 r180 bottom locked
J2 "691210910002" Wurth_691210910002 125,2364.17 r270 top
J5 "691210910002" Wurth_691210910002 124.99,3978.35 r270 top locked
J7 "61300511121" Wurth_61300511121 1251.02,4078 r90 top
J8 "PRPC010DAAN-RC" Sullins_xxxC010DAAN 1500,3828.35 r0 top locked
J20_1 "475890001" Molex_0475890001 2411.5,1576.46 r180 top (schematic designator J20)
J20_3 "475890001" Molex_0475890001 2411.5,3190.64 r180 top (schematic designator J20)
J20_4 "475890001" Molex_0475890001 2411.49,4804.81 r180 top (schematic designator J20)
J22 "PRPC010DAAN-RC" Sullins_xxxC010DAAN 1500,600 r0 top locked
J23 "61300511121" Wurth_61300511121 1250,2463.83 r90 top
J24 "PRPC010DAAN-RC" Sullins_xxxC010DAAN 1500,2214.17 r0 top locked
J28 "61300511121" Wurth_61300511121 1250,849.83 r90 top
J31 "691210910002" Wurth_691210910002 125,750 r270 top
J36 "61300511121" Wurth_61300511121 1248,349.83 r90 top
J37_1 "61300411121" WURTH_61300411121 2504.51,200 r180 top (schematic designator J37)
J37_3 "61300411121" WURTH_61300411121 2504.51,1814.17 r180 top (schematic designator J37)
J37_4 "61300411121" WURTH_61300411121 2504.51,3428.34 r180 top (schematic designator J37)
J39_1 "61300611121" WURTH_61300611121 2926.22,850.89 r90 top (schematic designator J39)
J39_3 "61300611121" WURTH_61300611121 2926.22,2465.06 r90 top (schematic designator J39)
J39_4 "61300611121" WURTH_61300611121 2926.21,4079.23 r90 top (schematic designator J39)
LBL1 "THT-14-423-10" Label_650x200 1574.8,2992.13 r180 bottom
LBL3 "THT-14-423-10" Label_650x200 1574.8,4606.3 r0 bottom
LBL4 "THT-14-423-10" Label_650x200 1574.8,1377.95 r180 bottom
Logo1 "Texas Instruments" TI_Stacked_Overlay_Small 866.14,1732.28 r0 top
Logo2 "Texas Instruments" TI_Stacked_Overlay_Small 866.14,118.11 r0 top
Logo3 "FCC disclaimer" FCC_disclaimer 1377.95,3110.24 r0 top
Logo4 "WEEE logo" WEEE_Minimum 1811.02,2401.57 r0 top
Logo5 "FCC disclaimer" FCC_disclaimer 1377.95,1496.06 r0 top
Logo6 "WEEE logo" WEEE_Minimum 1259.84,1220.47 r90 top
Logo16 "Texas Instruments" TI_Stacked_Overlay_Small 866.14,3346.46 r0 top
Logo17 "FCC disclaimer" FCC_disclaimer 1377.95,4724.41 r0 top
Logo18 "WEEE logo" WEEE_Minimum 1811.02,4015.75 r0 top
Q3 "BC846BLP4-7B" X2-DFN1006-3 203.13,481.54 r180 top value="65 V"
Q6 "BC846BLP4-7B" X2-DFN1006-3 1769.74,545.9 r180 top value="65 V"
R4 "CRCW040210R0JNED" 0402 849.56,1345.83 r270 top value=10
R6 "CRCW0402100KFKED" 0402 499.56,1350.11 r90 top value=100k
R8 "RMCF0603FG1M00" 0603 474.83,1088.79 r90 top value=1.00Meg
R9 "CRCW040210R0JNED" 0402 931.06,2249.41 r270 bottom value=10
R10 "CRCW04022M00FKED" 0402 381.06,2239.41 r270 top value=2.00Meg
R11 "CRCW0402499RFKED" 0402 461.06,2259.41 r180 top value=499
R12 "CRCW0402499RFKED" 0402 731.06,2259.41 r180 top value=499
R13 "CRCW0402499RFKED" 0402 461.06,2319.41 r180 top value=499
R14 "CRCW0402499RFKED" 0402 731.06,2329.41 r180 top value=499
R15 "CRCW04022M00FKED" 0402 381.06,2339.41 r270 top value=2.00Meg
R16 "PFC-W1206R-12-3241-B" 1206 901.06,2539.41 r180 top value=3.24k
R25_1 "CRCW040247K0JNED" 0402 2580,300 r0 top value=47k (schematic designator R25)
R25_3 "CRCW040247K0JNED" 0402 2580,1914.17 r0 top value=47k (schematic designator R25)
R25_4 "CRCW040247K0JNED" 0402 2579.99,3528.34 r0 top value=47k (schematic designator R25)
R27_1 "CRCW04023K32FKED" 0402 2206.46,479.57 r90 top value=3.32k (schematic designator R27)
R27_3 "CRCW04023K32FKED" 0402 2206.46,2093.74 r90 top value=3.32k (schematic designator R27)
R27_4 "CRCW04023K32FKED" 0402 2206.45,3707.91 r90 top value=3.32k (schematic designator R27)
R44 "CRCW040210R0JNED" 0402 786.16,4048.33 r225 bottom value=10
R45 "CRCW04022M00FKED" 0402 346.01,3933.7 r270 top value=2.00Meg
R46 "CRCW0402499RFKED" 0402 421.02,3960 r180 top value=499
R47 "CRCW0402499RFKED" 0402 669.28,3966.39 r180 top value=499
R48 "CRCW0402499RFKED" 0402 421.02,4032.13 r180 top value=499
R49 "CRCW0402499RFKED" 0402 669.28,4029.23 r180 top value=499
R50 "CRCW040210R0JNED" 0402 136.85,4129.89 r270 bottom value=10
R51 "CRCW04022M00FKED" 0402 346.01,4060.98 r270 top value=2.00Meg
R52 "CRCW0402100KFKED" 0402 841.97,4149.63 r180 top value=100k
R55_1 "CRCW04023K32FKED" 0402 2156.46,479.57 r90 top value=3.32k (schematic designator R55)
R55_3 "CRCW04023K32FKED" 0402 2156.46,2093.74 r90 top value=3.32k (schematic designator R55)
R55_4 "CRCW04023K32FKED" 0402 2156.45,3707.91 r90 top value=3.32k (schematic designator R55)
R56_1 "CRCW04023K32FKED" 0402 2106.22,479.57 r90 top value=3.32k (schematic designator R56)
R56_3 "CRCW04023K32FKED" 0402 2106.22,2093.74 r90 top value=3.32k (schematic designator R56)
R56_4 "CRCW04023K32FKED" 0402 2106.21,3707.91 r90 top value=3.32k (schematic designator R56)
R57_1 "CRCW04023K32FKED" 0402 2056.06,479.57 r90 top value=3.32k (schematic designator R57)
R57_3 "CRCW04023K32FKED" 0402 2056.06,2093.74 r90 top value=3.32k (schematic designator R57)
R57_4 "CRCW04023K32FKED" 0402 2056.06,3707.91 r90 top value=3.32k (schematic designator R57)
R65_1 "CRCW06031K00FKEA" 0603 2151.54,1119.38 r270 top value=1.00k (schematic designator R65)
R65_3 "CRCW06031K00FKEA" 0603 2151.54,2733.55 r270 top value=1.00k (schematic designator R65)
R65_4 "CRCW06031K00FKEA" 0603 2151.53,4347.72 r270 top value=1.00k (schematic designator R65)
R66_1 "CRCW06031K00FKEA" 0603 2096.38,1119.38 r270 top value=1.00k (schematic designator R66)
R66_3 "CRCW06031K00FKEA" 0603 2096.38,2733.55 r270 top value=1.00k (schematic designator R66)
R66_4 "CRCW06031K00FKEA" 0603 2096.37,4347.72 r270 top value=1.00k (schematic designator R66)
R70 "CRCW040210R0JNED" 0402 911.54,539.99 r90 top value=10
R71 "CRCW04024K70JNED" 0402 800,1025.44 r90 top value=4.7k
R72 "CRCW0603487KFKEA" 0603 527.8,1088.79 r270 top value=487k
R73 "CRCW04022M00FKED" 0402 80.41,945.83 r90 top value=2.00Meg
R74 "CRCW060310K0FKEA" 0603 681.81,878.74 r90 top value=10.0k
R75 "CRCW060310K0FKEA" 0603 628,878.74 r90 top value=10.0k
R76 "CRCW0402499RFKED" 0402 330,745.83 r180 top value=499
R77 "CRCW040210K0FKED" 0402 477.91,745.83 r180 top value=10.0k
R78 "CRCW060310K0FKEA" 0603 833.23,599.31 r270 top value=10.0k
R79 "CRCW06033K09FKEA" 0603 738.09,655.83 r180 bottom value=3.09k
R80 "CRCW060310K0FKEA" 0603 778,599.31 r270 top value=10.0k
R81 "CRCW0402499RFKED" 0402 330,787.99 r180 top value=499
R82 "CRCW040210K0FKED" 0402 477.91,788.39 r180 top value=10.0k
R83 "CRCW04022M00FKED" 0402 130,945.83 r270 top value=2.00Meg
R84 "CRCW040239K0JNED" 0402S 1645,457.91 r270 top value=39k
R85 "CRCW040210R0JNED" 0402 134.15,615.83 r0 bottom value=10
R86 "CRCW040268K0JNED" 0402 122.34,481.6 r180 top value=68k
R87 "CRCW04026K80JNED" 0402 268,481.54 r270 top value=6.8k
R109_1 "CRCW06031K00FKEA" 0603 2206.46,1119.38 r270 top value=1.00k (schematic designator R109)
R109_3 "CRCW06031K00FKEA" 0603 2206.46,2733.55 r270 top value=1.00k (schematic designator R109)
R109_4 "CRCW06031K00FKEA" 0603 2206.45,4347.72 r270 top value=1.00k (schematic designator R109)
R110 "CRCW0402249KFKED" 0402 1770,457.91 r270 top value=249k
R111 "CRCW0402100KJNED" 0402 1728.55,457.91 r270 top value=100k
R112 "CRCW0402100KJNED" 0402 1685,457.91 r270 top value=100k
R113 "CRCW0402100KJNED" 0402 1351.91,949.65 r0 bottom value=100k
R114 "CRCW04021K00JNED" 0402 1706.65,553.94 r270 top value=1.0k
R115 "CRCW040261K9FKED" 0402 1851.76,553.77 r270 top value=61.9k
R116_1 "CRCW04020000Z0EDHP" 0402 2409.03,1040 r0 top value=0 (schematic designator R116)
R116_3 "CRCW04020000Z0EDHP" 0402 2409.03,2654.17 r0 top value=0 (schematic designator R116)
R116_4 "CRCW04020000Z0EDHP" 0402 2409.02,4268.34 r0 top value=0 (schematic designator R116)
R117_1 "CRCW04020000Z0EDHP" 0402 2409.03,1090 r0 top value=0 (schematic designator R117)
R117_3 "CRCW04020000Z0EDHP" 0402 2409.03,2704.17 r0 top value=0 (schematic designator R117)
R117_4 "CRCW04020000Z0EDHP" 0402 2409.02,4318.34 r0 top value=0 (schematic designator R117)
R118_1 "CRCW04020000Z0EDHP" 0402 2361.03,1040 r0 top value=0 (schematic designator R118)
R118_3 "CRCW04020000Z0EDHP" 0402 2361.03,2654.17 r0 top value=0 (schematic designator R118)
R118_4 "CRCW04020000Z0EDHP" 0402 2361.02,4268.34 r0 top value=0 (schematic designator R118)
R119_1 "CRCW04020000Z0EDHP" 0402 2361.03,1090 r0 top value=0 (schematic designator R119)
R119_3 "CRCW04020000Z0EDHP" 0402 2361.03,2704.17 r0 top value=0 (schematic designator R119)
R119_4 "CRCW04020000Z0EDHP" 0402 2361.02,4318.34 r0 top value=0 (schematic designator R119)
R120 "CRCW040210R0JNED" 0402 275.1,3750 r0 bottom value=10
R121 "CRCW04020000Z0EDHP" 0402 841.02,4190 r180 top value=0
RT2 "PTS060301B100RP100" 0603S 196.85,2361.55 r90 bottom value=100ohm
S1_1 "434121025816" SW_434121025816 2160.39,259.38 r90 top (schematic designator S1)
S1_3 "434121025816" SW_434121025816 2160.39,1873.55 r90 top (schematic designator S1)
S1_4 "434121025816" SW_434121025816 2160.39,3487.72 r90 top (schematic designator S1)
S2_1 "434121025816" SW_434121025816 1976.22,259.38 r90 top (schematic designator S2)
S2_3 "434121025816" SW_434121025816 1976.22,1873.55 r90 top (schematic designator S2)
S2_4 "434121025816" SW_434121025816 1976.21,3487.72 r90 top (schematic designator S2)
SH-J1 "60900213421" Wurth_60900213421 1501.02,3373.36 r180 top
SH-J2 "60900213421" Wurth_60900213421 1501.02,3978.87 r180 top
SH-J3 "60900213421" Wurth_60900213421 1501.02,3776.07 r180 top
SH-J4 "60900213421" Wurth_60900213421 1501.02,3680 r180 top
SH-J5 "60900213421" Wurth_60900213421 1501.02,4078.35 r180 top
SH-J6 "60900213421" Wurth_60900213421 1501.02,3878 r180 top
SH-J7 "60900213421" Wurth_60900213421 1550,4230.54 r90 top
SH-J8 "60900213421" Wurth_60900213421 1500,2065.83 r180 top
SH-J9 "60900213421" Wurth_60900213421 1500,1761 r180 top
SH-J10 "60900213421" Wurth_60900213421 1500,2366.49 r180 top
SH-J11 "60900213421" Wurth_60900213421 1500,2265.83 r180 top
SH-J12 "60900213421" Wurth_60900213421 1545,2615.06 r90 top
SH-J13 "60900213421" Wurth_60900213421 1500,2461.43 r180 top
SH-J14 "60900213421" Wurth_60900213421 1500,2165.69 r180 top
SH-J15 "60900213421" Wurth_60900213421 1500,450.46 r180 top
SH-J16 "60900213421" Wurth_60900213421 1500,146.83 r180 top
SH-J17 "60900213421" Wurth_60900213421 1500,651.14 r180 top
SH-J18 "60900213421" Wurth_60900213421 1500,547.28 r180 top
SH-J19 "60900213421" Wurth_60900213421 1500,848.99 r180 top
SH-J20 "60900213421" Wurth_60900213421 1500,748.84 r180 top
SH-J21 "60900213421" Wurth_60900213421 1550,995.83 r90 top
TP1_1 "S2751-46R" Harwin_S2751-46R 2547.76,505.44 r180 top (schematic designator TP1)
TP1_3 "S2751-46R" Harwin_S2751-46R 2547.76,2119.61 r180 top (schematic designator TP1)
TP1_4 "S2751-46R" Harwin_S2751-46R 2547.75,3733.78 r180 top (schematic designator TP1)
TP2_1 "S2751-46R" Harwin_S2751-46R 2550,603.6 r180 top (schematic designator TP2)
TP2_3 "S2751-46R" Harwin_S2751-46R 2550,2217.77 r180 top (schematic designator TP2)
TP2_4 "S2751-46R" Harwin_S2751-46R 2549.99,3831.94 r180 top (schematic designator TP2)
U3 "ADS112U04IRTET" RTE0016D 1036.18,2369.25 r270 top
U6 "REF2125IDBVR" DBV0005A_N 600.23,1345.83 r270 top
U14 "ADS112U04IRTET" RTE0016D 956.64,4000 r225 top
U15 "LMT70YFQR" YFQ0004ACAC 182.9,4030.66 r180 bottom
U18_1 "TPS72733DSET" DSE0006A 1899.45,1352.9 r180 top (schematic designator U18)
U18_3 "TPS72733DSET" DSE0006A 1899.45,2967.08 r180 top (schematic designator U18)
U18_4 "TPS72733DSET" DSE0006A 1899.44,4581.24 r180 top (schematic designator U18)
U19 "LPV821DBVR" DBV0005A_N 691.65,1106.87 r0 top
U20_1 "MSP430FR2355TRHAR" RHA0040E 2140.71,793.94 r180 top (schematic designator U20)
U20_3 "MSP430FR2355TRHAR" RHA0040E 2140.71,2408.11 r180 top (schematic designator U20)
U20_4 "MSP430FR2355TRHAR" RHA0040E 2140.7,4022.28 r180 top (schematic designator U20)
U21 "ADS7142IRUGR" RUG0010A 806.03,394.07 r270 top
U22 "INA317IDGKR" DGK0008A_N 738.81,771.12 r0 bottom
U23 "TMP117AIDRVR" DRV0006B 239.25,750 r90 bottom
U24 "LMT01LPG" LPG0002A 159.15,555.83 r0 top
U30_1 "ISO7721D" D0008B_HV 2706.22,818.81 r270 top (schematic designator U30)
U30_3 "ISO7721D" D0008B_HV 2706.22,2432.98 r270 top (schematic designator U30)
U30_4 "ISO7721D" D0008B_HV 2706.21,4047.15 r270 top (schematic designator U30)
U31 "TMP235DCK" DCK0005A_N 211.02,3900 r270 bottom
U32_1 "TPS22946YZPR" YZP0006ADAD 2397.72,1165.84 r0 top (schematic designator U32)
U32_3 "TPS22946YZPR" YZP0006ADAD 2397.72,2780.02 r0 top (schematic designator U32)
U32_4 "TPS22946YZPR" YZP0006ADAD 2397.71,4394.18 r0 top (schematic designator U32)
Y1_1 "ECS-.327-12.5-34B-TR" ECS_ECX_31B 2366.22,907.97 r90 top (schematic designator Y1)
Y1_3 "ECS-.327-12.5-34B-TR" ECS_ECX_31B 2366.22,2522.14 r90 top (schematic designator Y1)
Y1_4 "ECS-.327-12.5-34B-TR" ECS_ECX_31B 2366.21,4136.31 r90 top (schematic designator Y1)
ZZ1 "This Assembly Note is for PCB labels only" AssemblyNoteLabel 469.29,5448 r0 top
ZZ2 "These assemblies are ESD sensitive, ESD precautions shall be observed." AssemblyNote 469.29,5339.11 r0 top
ZZ3 "These assemblies must be clean and free from flux and all contaminants. Use of no clean flux is not acceptable." AssemblyNote 469.29,5250.56 r0 top
ZZ4 "These assemblies must comply with workmanship standards IPC-A-610 Class 2, unless otherwise specified." AssemblyNote 469.29,5162 r0 top

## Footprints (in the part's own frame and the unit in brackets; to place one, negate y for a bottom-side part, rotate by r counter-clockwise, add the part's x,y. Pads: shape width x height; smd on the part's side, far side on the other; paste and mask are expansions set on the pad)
0402 [mm] "0402 from SM-752 data"
  rect 0.8x0.6 smd: 1(-0.6,0) 2(0.6,0)
  silkscreen extent -1.22,-0.52 1.22,0.52, body extent -0.55,-0.3 0.55,0.3, height 0.6
0402S [mil] "Based on C0402S footprint from PADS legacy"
  rect 15x24 smd: 1(-20,0) 2(20,0)
  body extent -22,-12 22,12, height 24
0603 [mm] "0603 from SM-752 data"
  rect 1x0.95 smd: 1(-0.8,0) 2(0.8,0)
  silkscreen extent -1.52,-0.69 1.52,0.69, body extent -0.87,-0.47 0.87,0.47, height 1
0603S [mil]
  rect 20x35 smd: 1(-30,0) 2(30,0)
  body extent -34,-19 34,19, height 39
0805_HV [mil] "0805 with 30mil clearance between pads"
  rect 50x63 smd: 1(-40,0) 2(40,0)
  silkscreen extent -74,-40 74,40, body extent -43,-29 43,29, height 57
1206 [mm] "1206 from SM-752 data"
  rect 1.3x1.85 smd: 1(-1.45,0) 2(1.45,0)
  silkscreen extent -2.4,-1.21 2.4,1.21, body extent -1.7,-0.9 1.7,0.9, height 1.35
AssemblyNote [mil] "Assembly Note"
AssemblyNoteLabel [mil] "Assembly Note for PCB Labels"
D0008B_HV [mm] "SOIC, 8-Leads, Body 4.9x3.9mm, Pitch 1.27mm, HV / Isolation option"
  rrect17% 1.4x0.6 smd: 1(-2.75,1.905) 2(-2.75,0.635) 3(-2.75,-0.635) 4(-2.75,-1.905) 5(2.75,-1.905) 6(2.75,-0.635) 7(2.75,0.635) 8(2.75,1.905)
  silkscreen extent -3.3,-2.5 0.9,2.5, body extent -3,-2.45 3,2.45, height 1.63
DBV0005A_N [mm] "SOT23, 5-Leads, Body 2.9x1.6mm, Pitch 0.95mm, Lead Span 2.8mm, IPC Medium Density"
  rrect17% 1x0.6 smd: 1(-1.375,0.95) 2(-1.375,0) 3(-1.375,-0.95) 4(1.375,-0.95) 5(1.375,0.95)
  silkscreen extent -1.63,-1.55 0.38,1.55, body extent -1.42,-1.46 1.42,1.46, height 1.09
DCK0005A_N [mm] "SOT353, 5-Leads, Body 2x1.3mm, Pitch 0.65mm, Lead Span 2.1mm, IPC Medium Density"
  rrect25% 0.85x0.4 smd: 1(-1.125,0.65) 2(-1.125,0) 3(-1.125,-0.65) 4(1.125,-0.65) 5(1.125,0.65)
  silkscreen extent -1.48,-1.02 0.55,1.1, body extent -1.14,-1 1.14,1, height 0.95
DGK0008A_N [mm] "TSOP, 8-Leads, Body 3x3mm, Pitch 0.65mm, IPC Medium Density"
  oval 1.35x0.45 smd: 1(-2.225,0.975) 2(-2.225,0.325) 3(-2.225,-0.325) 4(-2.225,-0.975) 5(2.225,-0.975) 6(2.225,-0.325) 7(2.225,0.325) 8(2.225,0.975)
  silkscreen extent -2.75,-1.55 0.95,1.55, body extent -2.45,-1.5 2.45,1.5, height 0.96
DRV0006B [mm] "SON, 6-Leads, Body 2x2mm, Pitch 0.65mm, TI Recommended"
  rrect33% 0.45x0.3 smd: 1(-0.975,0.65) 2(-0.975,0) 3(-0.975,-0.65) 4(0.975,-0.65) 5(0.975,0) 6(0.975,0.65)
  silkscreen extent -1.05,-1.2 1.05,1.2, body extent -1.05,-1.05 1.05,1.05, height 0.81
DSE0006A [mm] "TI recommended land pattern"
  rect 0.66x0.25 smd: 1(-0.62,0.5)
  rect 0.7x0.25 smd: 2(-0.6,0) 3(-0.6,-0.5) 4(0.6,-0.5) 5(0.6,0) 6(0.6,0.5)
  Top Layer region: -0.3,0.625 -0.25,0.625 -0.15,0.525 -0.15,0.375 -0.3,0.375
  silkscreen extent -0.9,-0.92 0.9,0.92, body extent -0.77,-0.77 0.77,0.77, height 0.8
ECS_ECX_31B [mm] "SMD, 2-Leads, Body 3.2x1.5mm"
  rrect9% 1.1x1.9 smd: 1(-1.25,0) 2(1.25,0)
  body extent -1.6,-0.75 1.6,0.75, height 0.9
FCC_disclaimer [mil]
Fiducial10-20 [mm]
  round 1 smd mask+0.5: 1(0,0)
  Top Layer keep-out circle w1.178: c0,0 r0.5
FUSE_0ZCJ_085 [mm] "SMD, 2-Leads, Body 3.25x1.65mm"
  rrect10% 1x1.9 smd: 1(-1.5,0) 2(1.5,0)
  body extent -1.75,-0.9 1.75,0.9, height 0.85
Harwin_S2751-46R [mm] "Test Point, SMT"
  rect 2.2x1.4 smd: 1(0,0)
  body extent -1,-0.6 1,0.6, height 1.4
Keystone_1902C [mil] "Hex Standoff, 4-40 threaded, nylon"
  round 1 on Mech4: 0(0,0)
  body extent -145,-126 146,126, height 501
Label_650x200 [mil] "Thermal Transfer Label"
  round 1 on Mech14: 0(0,0)
  silkscreen extent -325,-100 325,100, body extent -325,-100 325,100, height 1
LPG0002A [mm] "TO, 2-Leads, Body 4x1.52mm"
  rrect9% 1.07x1.7 hole 0.75: 1(-1.27,0)
  rrect100% 1.07x1.7 hole 0.75: 2(1.27,0)
  round 0.75 hole 0.75 unplated paste+0 mask+0: MH(0,0)
  silkscreen extent -2.21,-1.25 2.21,1.25, body extent -2,-0.98 2,0.54, height 5.06
Molex_0475890001 [mm] "Molex"
  rrect25% 0.4x1.35 smd: 1(-1.3,4.125) 2(-0.65,4.125) 3(0,4.125) 4(0.65,4.125) 5(1.3,4.125)
  oval 1.05x1.3 hole 0.7 slot 0.85 at 90 deg: 6(2.225,4.45) 11(-2.225,4.45)
  oval 0.8x2 hole 0.6 slot 1.3 at 90 deg: 7(4.175,1.45) 10(-4.175,1.45)
  rrect6% 1.8x2 smd: 8(1.15,1.45) 9(-1.15,1.45)
  Top Layer region: 2.6,0.45 2.6,2.45 4.175,2.45 4.175,0.45
  Top Layer region: -4.175,0.45 -4.175,2.45 -2.6,2.45 -2.6,0.45
  silkscreen extent -3.75,2.85 3.75,4.3, body extent -4.32,-1.3 4.33,4.59, height 2.81
"NY PMS 440 0025 PH" [mm] "4-40 nylon screw and mounting hole"
  round 8 hole 3.2: 1(0,0)
  body extent -3.31,-3.3 3.3,3.3, height 2.69
RHA0040E [mm] "QFN, 40-Leads, Body 6x6mm, Pitch 0.5mm, Thermal Pad 2.9x2.9mm, TI Recommended"
  oval 0.6x0.23 smd mask+0.07: 1(-2.9,2.25) 2(-2.9,1.75) 3(-2.9,1.25) 4(-2.9,0.75) 5(-2.9,0.25) 6(-2.9,-0.25) 7(-2.9,-0.75) 8(-2.9,-1.25) 9(-2.9,-1.75) 10(-2.9,-2.25) 21(2.9,-2.25) 22(2.9,-1.75) 23(2.9,-1.25) 24(2.9,-0.75) 25(2.9,-0.25) 26(2.9,0.25) 27(2.9,0.75) 28(2.9,1.25) 29(2.9,1.75) 30(2.9,2.25)
  oval 0.23x0.6 smd mask+0.07: 11(-2.25,-2.9) 12(-1.75,-2.9) 13(-1.25,-2.9) 14(-0.75,-2.9) 15(-0.25,-2.9) 16(0.25,-2.9) 17(0.75,-2.9) 18(1.25,-2.9) 19(1.75,-2.9) 20(2.25,-2.9) 31(2.25,2.9) 32(1.75,2.9) 33(1.25,2.9) 34(0.75,2.9) 35(0.25,2.9) 36(-0.25,2.9) 37(-0.75,2.9) 38(-1.25,2.9) 39(-1.75,2.9) 40(-2.25,2.9)
  rect 3.52x2.62 smd paste-1.747: 41(0,0)
  silkscreen extent -3.22,-3.22 3.22,3.22, body extent -3.08,-3.08 3.08,3.08, height 1.01
RTE0016D [mm] "QFN, 16-Leads, Body 3x3mm, Pitch 0.5mm"
  oval 0.6x0.24 smd: 1(-1.4,0.75) 2(-1.4,0.25) 3(-1.4,-0.25) 4(-1.4,-0.75) 9(1.4,-0.75) 10(1.4,-0.25) 11(1.4,0.25) 12(1.4,0.75)
  oval 0.24x0.6 smd: 5(-0.75,-1.4) 6(-0.25,-1.4) 7(0.25,-1.4) 8(0.75,-1.4) 13(0.75,1.4) 14(0.25,1.4) 15(-0.25,1.4) 16(-0.75,1.4)
  rect 0.8x0.8 smd paste-0.85: 17(0,0)
  silkscreen extent -1.72,-1.73 1.72,1.73, body extent -1.57,-1.57 1.58,1.58, height 0.81
RUG0010A [mm] "QFN, 10-Leads, Body 2x1.5mm. Pitch 0.5mm, TI Recommended"
  rect 0.55x0.25 smd: 1(-0.675,0.75) 4(-0.675,-0.75) 6(0.675,-0.75) 9(0.675,0.75)
  rect 0.55x0.2 smd: 2(-0.675,0.25) 3(-0.675,-0.25) 7(0.675,-0.25) 8(0.675,0.25)
  rect 0.3x0.575 smd: 5(0,-0.913) 10(0,0.913)
  silkscreen extent -0.9,-1.15 0.9,1.15, body extent -0.77,-1.02 0.77,1.02, height 0.41
SOT-23L [mm] "SOT23, 3-Leads, Body 2.9x1.3mm, Pitch 0.95mm, Lead Span 2.5mm, IPC High Density"
  rrect50% 0.8x0.6 smd: 1(-1.1,0.95) 2(-1.1,-0.95) 3(1.1,0)
  silkscreen extent -1.5,-1.5 0.7,1.5, body extent -1.16,-1.45 1.21,1.45, height 1
SOT-323 [mm] "Diodes Inc recommended land pattern.  2016-02-24"
  rrect21% 0.6x0.47 smd: 1(-0.95,0.65) 2(-0.95,-0.65) 3(0.95,0)
  silkscreen extent -1.14,-1.22 0.77,1.22, body extent -1.13,-1.13 1.12,1.12, height 1.13
Sullins_xxxC010DAAN [mm] "Header, 2.54mm, 10x2, TH"
  rect 1.5x1.5 hole 1: 1(-1.27,11.43)
  round 1.5 hole 1: 2(1.27,11.43) 3(-1.27,8.89) 4(1.27,8.89) 5(-1.27,6.35) 6(1.27,6.35) 7(-1.27,3.81) 8(1.27,3.81) 9(-1.27,1.27) 10(1.27,1.27) 11(-1.27,-1.27) 12(1.27,-1.27) 13(-1.27,-3.81) 14(1.27,-3.81) 15(-1.27,-6.35) 16(1.27,-6.35) 17(-1.27,-8.89) 18(1.27,-8.89) 19(-1.27,-11.43) 20(1.27,-11.43)
  silkscreen extent -2.5,-12.7 2.5,13.14, body extent -2.5,-12.7 2.5,12.7, height 8.34
SW_434121025816 [mm] "SMD, 2-Leads, Body 6x3.9mm, Pitch 6.5mm"
  rect 1.5x1.4 smd: 1(-3.25,0) 2(3.25,0)
  silkscreen extent -3,-1.95 3,1.95, body extent -3.65,-1.95 3.65,1.95, height 2.5
TI_Stacked_Overlay_Small [mil]
  silkscreen extent -418,-98 418,98
WEEE_Minimum [mil] "WEEElie bin"
  silkscreen extent -95,-172 99,104
WL-SMCC_0402_Green [mm] "SMD, 2-Leads, Body 1x0.5mm"
  rrect17% 0.6x0.6 smd: 1(-0.55,0) 2(0.55,0)
  body extent -0.5,-0.25 0.5,0.25, height 0.39
Wurth_60900213421 [mil] "Shunt, 2.54mm, Black"
  round 1 on Mech3: 0(0,0)
  body extent -98,-48 98,48, height 338
WURTH_61300411121 [mm] "Header, 2.54mm, 4x1, TH"
  rrect50% 1.65x1.65 hole 1.15: 1(-3.81,0)
  round 1.65 hole 1.15: 2(-1.27,0) 3(1.27,0) 4(3.81,0)
  body extent -5.08,-1.27 5.08,1.27, height 8.54
Wurth_61300511121 [mm] "Header, 2.54mm, 5x1, TH"
  rrect50% 1.65x1.65 hole 1.1: 1(-5.08,0)
  round 1.65 hole 1.1: 2(-2.54,0) 3(0,0) 4(2.54,0) 5(5.08,0)
  body extent -6.35,-1.27 6.35,1.27, height 8.54
WURTH_61300611121 [mm] "Header, 2.54mm, 6x1, TH"
  rrect50% 1.65x1.65 hole 1.15: 1(-6.35,0)
  round 1.65 hole 1.15: 2(-3.81,0) 3(-1.27,0) 4(1.27,0) 5(3.81,0) 6(6.35,0)
  body extent -7.62,-1.27 7.62,1.27, height 8.54
Wurth_691210910002 [mm] "Receptacle, 2.54mm, 2x1, R/A, TH"
  rrect50% 1.8x1.8 hole 1.3: 1(-1.27,0)
  round 1.8 hole 1.3: 2(1.27,0)
  silkscreen extent -3.2,-3.25 2.77,3.25, body extent -2.77,-3.25 2.77,3.25, height 8.85
X2-DFN1006-3 [mm] "DFN, 3-Leads, Body 1x0.6mm"
  rrect40% 0.4x0.25 smd: 1(-0.35,0.225) 2(-0.35,-0.225)
  rrect25% 0.4x0.7 smd: 3(0.35,0)
  body extent -0.52,-0.33 0.52,0.33, height 0.4
YFQ0004ACAC [mm] "WCSP, 4-Leads, Body 0.84x0.84mm, Pitch 0.4mm"
  round 0.23 smd paste-0.13 mask+0.038: A1(-0.2,0.2) A2(0.2,0.2) B1(-0.2,-0.2) B2(0.2,-0.2)
  silkscreen extent -0.51,-0.51 0.51,0.51, body extent -0.42,-0.42 0.42,0.42, height 0.58
YZP0006ADAD [mm] "BGA, 6-Balls, Body 1.388x0.888mm, Pitch 0.5mm"
  round 0.23 smd paste-0.12: A1(-0.25,0.5) A2(0.25,0.5) B1(-0.25,0) B2(0.25,0) C1(-0.25,-0.5) C2(0.25,-0.5)
  silkscreen extent -0.6,-0.85 0.6,0.85, body extent -0.46,-0.71 0.46,0.71, height 0.51

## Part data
C1 C2 C7 C9 C11 C13 C15 C19 C39 C41 C42 C45 C51 C53 C66_1 C66_3 C66_4 C68 C69 C72 C73 C85_1 C85_3 C85_4 C86_1 C86_3 C86_4: library part CMP-0064931-4, "CAP, CERM, 0.1 uF, 10 V,+/- 10%, X7R, 0603", Cap_Case=0603, Manufacturer="Wurth Elektronik", Supplier Part Number 1=732-7939-1-ND, TempCo=X7R, Tolerance_%=10%, Value1=Unknown, Value2=10V, ValueDisplayed=0.1uF
C6 C65_1 C65_3 C65_4: library part CMP-0007691-2, "CAP, CERM, 10 uF, 10 V, +/- 10%, X7R, 0805", Cap_Case=0805, Manufacturer="Wurth Elektronik", Supplier Part Number 1=710-885012207026, TempCo=X7R, Tolerance_%=10%, Value1=Unknown, Value2=10V, ValueDisplayed=10uF
C10 C12 C16 C18 C38 C40 C44 C54 C67 C74: library part CMP-0006824-5, "CAP, CERM, 1 uF, 16 V, +/- 20%, X5R, 0603", Cap_Case=0603, Manufacturer="Wurth Elektronik", Supplier Part Number 1=710-885012106017, TempCo=X5R, Tolerance_%=20%, Value1=Unknown, Value2=16V, ValueDisplayed=1uF
C14 C17 C37 C43: library part CMP-0006998-4, "CAP, CERM, 0.01 uF, 50 V, +/- 5%, C0G/NP0, 0603", Cap_Case=0603, Manufacturer=TDK, Supplier Part Number 1=445-14056-1-ND, TempCo=C0G/NP0, Tolerance_%=5%, Value1=Unknown, Value2=50V, ValueDisplayed=0.01uF
C21_1 C21_3 C21_4: library part CMP-0006846-4, "CAP, CERM, 1000 pF, 25 V, +/- 10%, C0G/NP0, 0603", Cap_Case=0603, Manufacturer=Kemet, Supplier Part Number 1=399-7833-1-ND, TempCo=C0G/NP0, Tolerance_%=10%, Value1="0 ohm", Value2=25V, ValueDisplayed=1000pF
C22_1 C22_3 C22_4 C23_1 C23_3 C23_4: library part CMP-0006375-2, "CAP, CERM, 12 pF, 25 V, +/- 5%, C0G/NP0, 0402", Cap_Case=0402, Manufacturer=MuRata, Supplier Part Number 1=81-GRM1555C1E120JA1D, TempCo=C0G/NP0, Tolerance_%=5%, Value1=Unknown, Value2=25V, ValueDisplayed=12pF
C34_1 C34_3 C34_4 C83_1 C83_3 C83_4 C84_1 C84_3 C84_4 C89_1 C89_3 C89_4: library part CMP-0082011-1, "CAP, CERM, 1 µF, 10 V,+/- 10%, X7R, 0603", Cap_Case=0603, Manufacturer=Samsung, Supplier Part Number 1=1276-1946-1-ND, TempCo=X7R, Tolerance_%=10%, Value2=10V, ValueDisplayed=1µF
C46 C90: library part CMP-0007015-5, "CAP, CERM, 0.047 uF, 50 V, +/- 10%, X5R, 0603", Cap_Case=0603, Manufacturer=TDK, Supplier Part Number 1=445-14155-1-ND, TempCo=X5R, Tolerance_%=10%, Value1="0.049007 ohm", Value2=50V, ValueDisplayed=0.047uF
C70: library part CMP-0007137-5, "CAP, CERM, 1 uF, 16 V, +/- 20%, X7R, AEC-Q200 Grade 1, 0603", Cap_Case=0603, Manufacturer=MuRata, TempCo=X7R, Tolerance_%=20%, Value1=Unknown, Value2=16V, ValueDisplayed=1uF
C87: library part CMP-0006355-2, "CAP, CERM, 0.01 uF, 50 V, +/- 10%, C0G/NP0, 0402", Cap_Case=0402, Manufacturer=MuRata, Supplier Part Number 1=490-4762-1-ND, TempCo=C0G/NP0, Tolerance_%=10%, Value1=Unknown, Value2=50V, ValueDisplayed=0.01uF
C88: library part CMP-0006215-2, "CAP, CERM, 10 pF, 50 V, +/- 5%, C0G/NP0, 0402", Cap_Case=0402, Manufacturer="Wurth Elektronik", Supplier Part Number 1=732-7469-1-ND, TempCo=C0G/NP0, Tolerance_%=5%, Value1=Unknown, Value2=50V, ValueDisplayed=10pF
D1_1 D1_3 D1_4 D2_1 D2_3 D2_4 D9_1 D9_3 D9_4 D10_1 D10_3 D10_4: library part CMP-0081765-2, "LED, Green, SMD", Color=Green, Manufacturer="Wurth Elektronik", Power_TotalModule=99mW, Value1=0.099W, Value2=3.2V
D3 D4 D7 D8 D12 D13: library part CMP-0076968-2, "Diode, Switching, 70 V, 0.215 A, SOT-23", Manufacturer="Micro Commercial Components", Value1=0.215A, Value2=V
